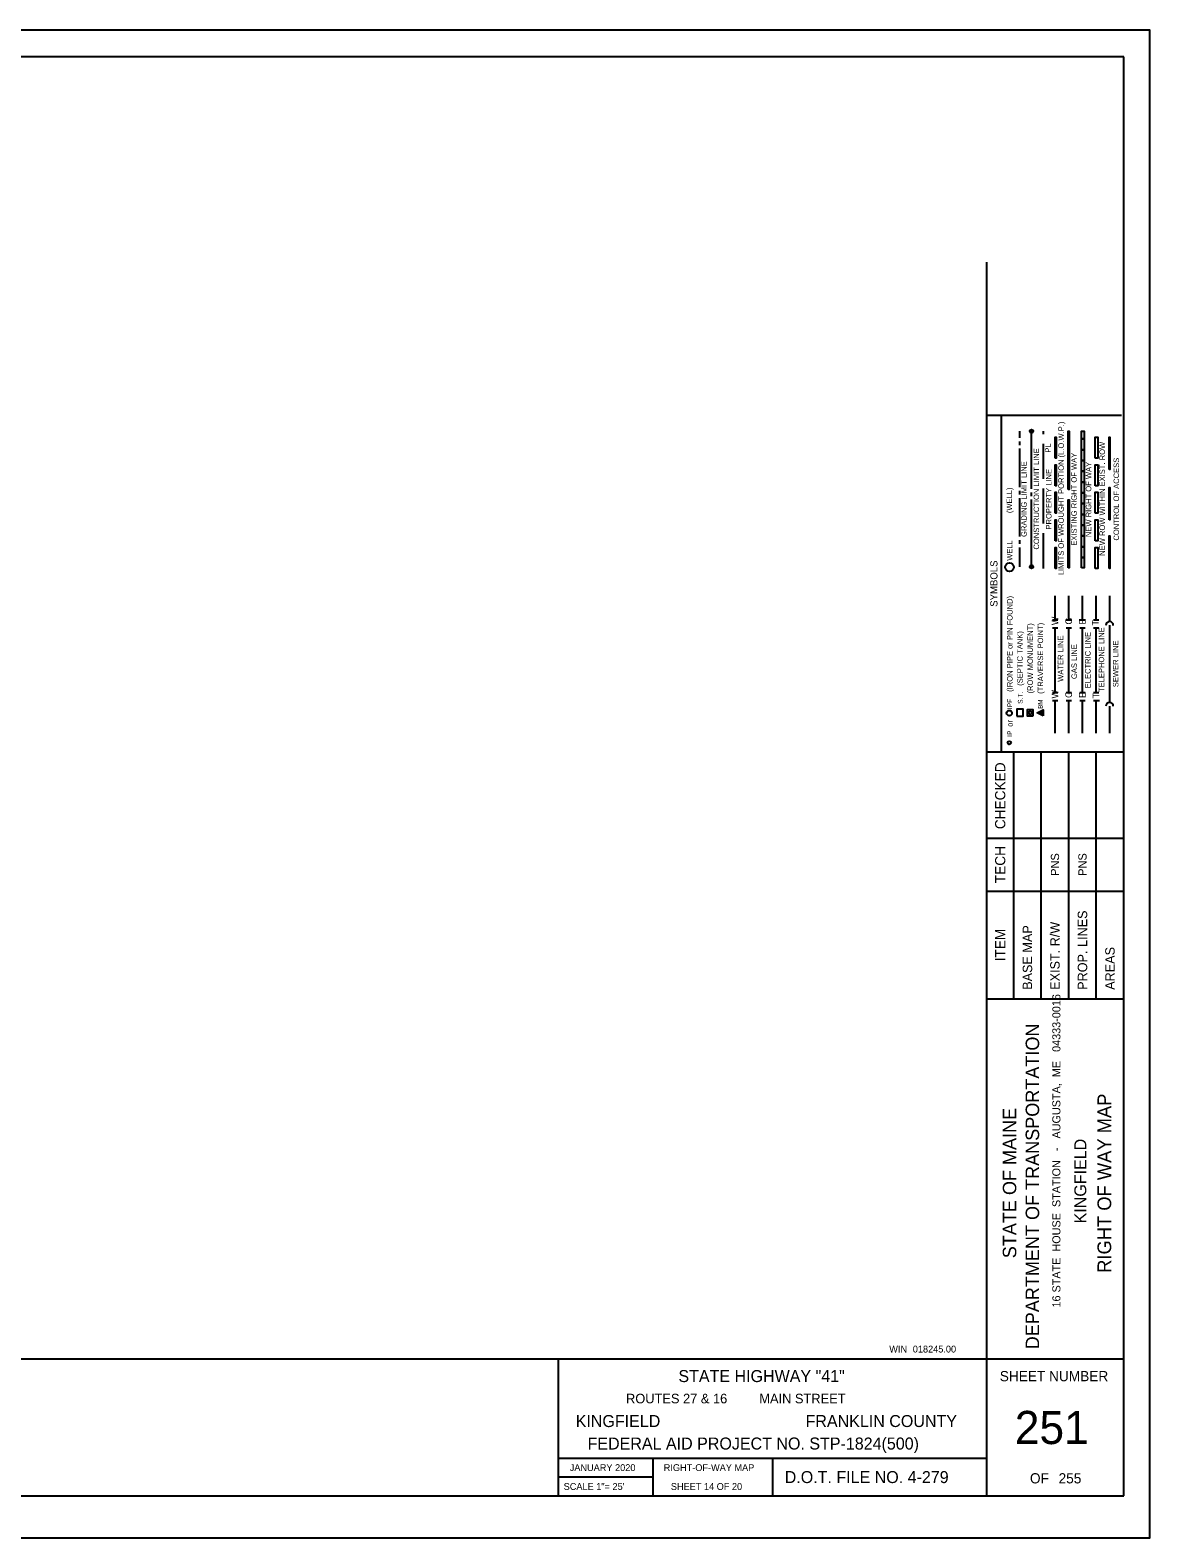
# Model space of a CAD drawing. Extents: x -40 to 810, y -90 to 460.
# Drawn here: x 401 to 810, y -90 to 460 of the extents above; entities that cross this region are included whole.
import ezdxf

# ---------------------------------------------------------------- set-up
doc = ezdxf.new("R2010")
doc.units = 0
for name, color, linetype in [('Border', 7, 'Continuous'), ('HIGHWAY_TITLE', 7, 'Continuous'), ('PLOT BOUNDARY', 7, 'Continuous')]:
    doc.layers.add(name, color=color, linetype=linetype)

msp = doc.modelspace()

# ---------------------------------------------------------------- linework, layer by layer
at = {"layer": 'Border'}
for p, q in [((800, 450), (0, 450)), ((800, -74.98), (800, 450)), ((750, -75), (750, 375.03)), ((750, 319.31), (799.21, 319.31)), ((755.25, 319.31), (755.25, 196.41)), ((762.03, 310.99), (762.03, 313.37)), ((762.03, 308.37), (762.03, 309.68)), ((766.35, 292.38), (766.35, 312.74)), ((770.67, 312.38), (770.67, 313.37)), ((770.67, 296.04), (770.67, 308.84)), ((762.03, 300.02), (762.03, 307.05)), ((762.03, 292.98), (762.03, 300.02)), ((762.03, 290.35), (762.03, 291.67)), ((770.67, 279.71), (770.67, 292.5)), ((762.03, 282), (762.03, 289.04)), ((766.35, 289.76), (766.35, 291.07)), ((766.35, 264.62), (766.35, 288.44)), ((762.03, 274.97), (762.03, 282)), ((770.67, 263.37), (770.67, 276.16)), ((762.03, 272.34), (762.03, 273.66)), ((762.03, 263.99), (762.03, 271.03)), ((774.99, 244.64), (774.99, 253.3)), ((779.97, 244.64), (779.97, 253.3)), ((784.94, 244.64), (784.94, 253.3)), ((789.92, 244.64), (789.92, 253.3)), ((794.9, 244.05), (794.9, 253.3)), ((774.01, 244.64), (775.98, 244.64)), ((778.98, 244.64), (780.95, 244.64)), ((783.96, 244.64), (785.93, 244.64)), ((788.94, 244.64), (790.9, 244.64)), ((794.9, 232.83), (794.9, 242.67)), ((774.01, 241.69), (775.98, 241.69)), ((774.99, 218.06), (774.99, 241.69)), ((778.98, 241.69), (780.95, 241.69)), ((779.97, 229.87), (779.97, 241.69)), ((783.96, 241.69), (785.93, 241.69)), ((784.94, 229.87), (784.94, 241.69)), ((788.94, 241.69), (790.9, 241.69)), ((789.92, 229.87), (789.92, 241.69)), ((794.9, 214.52), (794.9, 232.83)), ((779.97, 218.06), (779.97, 229.87)), ((784.94, 218.06), (784.94, 229.87)), ((789.92, 218.06), (789.92, 229.87)), ((774.01, 218.06), (775.98, 218.06)), ((774.01, 215.11), (775.98, 215.11)), ((774.99, 203.3), (774.99, 215.11)), ((778.98, 218.06), (780.95, 218.06)), ((778.98, 215.11), (780.95, 215.11)), ((779.97, 203.3), (779.97, 215.11)), ((783.96, 218.06), (785.93, 218.06)), ((783.96, 215.11), (785.93, 215.11)), ((784.94, 203.3), (784.94, 215.11)), ((788.94, 218.06), (790.9, 218.06)), ((788.94, 215.11), (791.1, 215.11)), ((789.92, 203.3), (789.92, 215.11)), ((794.9, 203.3), (794.9, 213.14)), ((750, 196.41), (800, 196.41)), ((759.84, 106.28), (759.84, 196.41)), ((769.88, 106.28), (769.88, 196.41)), ((779.92, 106.28), (779.92, 196.41)), ((789.96, 106.28), (789.96, 196.41)), ((750, 164.9), (800, 164.9)), ((750, 145.57), (800, 145.57)), ((750, 106.28), (800, 106.28)), ((0, -24.98), (800, -24.98)), ((593.75, -75), (593.75, -24.98)), ((593.75, -61.24), (750, -61.24)), ((628.12, -61.24), (628.12, -75)), ((671.87, -61.24), (671.87, -75)), ((628.12, -68.12), (593.75, -68.12)), ((0, -75), (800, -75))]:
    msp.add_line(p, q, dxfattribs=at)
for points in [[(774.99, 303.53), (774.99, 311.2), (775.39, 311.2), (775.39, 303.53)], [(779.71, 292.11), (779.71, 313.37), (780.1, 313.37), (780.1, 292.11)], [(784.62, 310.61), (784.62, 313.37), (785.6, 313.37), (785.6, 310.61)], [(784.62, 306.67), (784.62, 310.61), (785.6, 310.61), (785.6, 306.67)], [(789.59, 303.53), (789.59, 311.2), (790.58, 311.2), (790.58, 303.53)], [(794.7, 299.39), (794.7, 311.2), (794.9, 311.2), (794.9, 299.39)], [(784.62, 302.74), (784.62, 306.67), (785.6, 306.67), (785.6, 302.74)], [(784.62, 298.8), (784.62, 302.74), (785.6, 302.74), (785.6, 298.8)], [(774.99, 293.49), (774.99, 301.16), (775.39, 301.16), (775.39, 293.49)], [(784.62, 294.86), (784.62, 298.8), (785.6, 298.8), (785.6, 294.86)], [(789.59, 293.49), (789.59, 301.16), (790.58, 301.16), (790.58, 293.49)], [(784.62, 290.93), (784.62, 294.86), (785.6, 294.86), (785.6, 290.93)], [(794.7, 281.08), (794.7, 292.9), (794.9, 292.9), (794.9, 281.08)], [(774.99, 283.45), (774.99, 291.12), (775.39, 291.12), (775.39, 283.45)], [(779.71, 263.56), (779.71, 288.37), (780.1, 288.37), (780.1, 263.56)], [(784.62, 286.99), (784.62, 290.93), (785.6, 290.93), (785.6, 286.99)], [(784.62, 283.05), (784.62, 286.99), (785.6, 286.99), (785.6, 283.05)], [(789.59, 283.45), (789.59, 291.12), (790.58, 291.12), (790.58, 283.45)], [(774.99, 273.41), (774.99, 281.08), (775.39, 281.08), (775.39, 273.41)], [(784.62, 279.12), (784.62, 283.05), (785.6, 283.05), (785.6, 279.12)], [(789.59, 273.41), (789.59, 281.08), (790.58, 281.08), (790.58, 273.41)], [(784.62, 275.18), (784.62, 279.12), (785.6, 279.12), (785.6, 275.18)], [(784.62, 271.24), (784.62, 275.18), (785.6, 275.18), (785.6, 271.24)], [(794.7, 263.37), (794.7, 275.18), (794.9, 275.18), (794.9, 263.37)], [(774.99, 263.37), (774.99, 271.04), (775.39, 271.04), (775.39, 263.37)], [(784.62, 267.3), (784.62, 271.24), (785.6, 271.24), (785.6, 267.3)], [(789.59, 263.37), (789.59, 271.04), (790.58, 271.04), (790.58, 263.37)], [(784.62, 263.56), (784.62, 267.3), (785.6, 267.3), (785.6, 263.56)]]:
    msp.add_lwpolyline(points, close=True, dxfattribs=at)
for points in [[(760.95, 209.4), (763.31, 209.4), (763.31, 211.96), (760.95, 211.96), (760.95, 209.4)], [(766.98, 209.56), (766.98, 211.81), (764.73, 211.81), (764.73, 209.56), (766.98, 209.56)], [(770.54, 209.62), (768.44, 210.67), (770.54, 211.73), (770.54, 209.62)]]:
    msp.add_lwpolyline(points, dxfattribs=at)
for centre, radius in [((766.35, 313.37), 0.625), ((766.35, 313.37), 0.15), ((766.35, 313.37), 0.05), ((758.29, 263.81), 1.57), ((766.35, 263.99), 0.625), ((766.35, 263.99), 0.15), ((766.35, 263.99), 0.05), ((758.24, 210.59), 0.966), ((765.86, 210.68), 0.563), ((769.86, 210.68), 0.281), ((758.24, 199.76), 0.625)]:
    msp.add_circle(centre, radius, dxfattribs=at)
for centre in [(794.84, 242.59), (794.84, 213.06)]:
    msp.add_arc(centre, 1.35, 0, 180, dxfattribs=at)
at = {"layer": 'PLOT BOUNDARY'}
msp.add_lwpolyline([(-40.47, -90.29), (809.53, -90.29), (809.53, 459.71), (-40.47, 459.71)], close=True, dxfattribs=at)

# ---------------------------------------------------------------- texts
at = {"layer": 'Border'}
for s, height, rotation, p in [('LIMITS OF WROUGHT PORTION (L.O.W.P.)', 1.9996, 90, (778.14, 260.91)), ('PL', 2, 90, (773.35, 305.59)), ('NEW ROW WITHIN EXIST. ROW', 1.9996, 90, (793.14, 267.96)), ('CONSTRUCTION LIMIT LINE', 1.9996, 90, (769.11, 270.22)), ('EXISTING RIGHT OF WAY', 1.9996, 90, (782.86, 271.64)), ('CONTROL OF ACCESS', 1.9996, 90, (798.29, 273.5)), ('GRADING LIMIT LINE', 1.9996, 90, (764.59, 274.83)), ('PROPERTY LINE', 1.9996, 90, (773.63, 277.54)), ('NEW RIGHT OF WAY', 1.9996, 90, (788.16, 274.78)), ('(WELL)', 2, 90, (759.23, 283.52)), ('WELL', 1.969, 90, (759.36, 266.17)), ('SYMBOLS', 2.614, 90, (753.93, 249.35)), ('(IRON PIPE or PIN FOUND)', 1.9996, 90, (759.41, 218.34)), ('(ROW MONUMENT)', 1.9996, 90, (766.85, 217.74)), ('(TRAVERSE POINT)', 1.9996, 90, (770.58, 217.59)), ('W', 2.46, 90, (776.17, 242.67)), ('G', 2.46, 90, (781.15, 242.87)), ('E', 2.46, 90, (786.13, 242.87)), ('T', 2.46, 90, (790.9, 242.47)), ('(SEPTIC TANK)', 1.9996, 90, (763.13, 220.53)), ('WATER LINE', 2, 90, (777.95, 222)), ('ELECTRIC LINE', 1.9996, 90, (787.9, 219.64)), ('TELEPHONE LINE', 1.9996, 90, (792.87, 218.26)), ('GAS LINE', 2, 90, (782.92, 222.98)), ('SEWER LINE', 2, 90, (798.05, 220.03)), ('IPF', 1.749, 90, (759.28, 212.02)), ('S.T.', 1.749, 90, (763.12, 213.93)), ('BM', 1.641, 90, (770.4, 212.13)), ('W', 2.46, 90, (776.17, 215.9)), ('G', 2.46, 90, (781.15, 216.09)), ('E', 2.46, 90, (786.13, 216.09)), ('T', 2.46, 90, (791.1, 215.9)), ('IP', 1.749, 90, (759.28, 201.92)), ('or', 2, 90, (759.47, 205.59)), ('CHECKED', 3.726, 90, (756.78, 168.23)), ('TECH', 3.726, 90, (756.78, 148.51)), ('PROP. LINES', 3.4449, 90, (786.66, 109.63)), ('BASE MAP', 3.445, 90, (766.58, 109.63)), ('EXIST. R/W', 3.445, 90, (776.62, 109.63)), ('ITEM', 3.726, 90, (756.78, 120.01)), ('AREAS', 3.445, 90, (796.7, 109.63)), ('16 STATE  HOUSE  STATION   -   AUGUSTA,  ME   04333-0016', 2.9528, 90, (776.89, -6.27)), ('DEPARTMENT OF TRANSPORTATION', 4.9217, 90, (769.13, -21.51)), ('STATE OF MAINE', 4.9217, 90, (760.79, 11.72)), ('RIGHT OF WAY MAP', 4.9996, 90, (795.42, 6.39)), ('D.O.T. FILE NO. 4-279', 4.375, 360, (676.28, -70.31))]:
    msp.add_text(s, height=height, rotation=rotation, dxfattribs=at).set_placement(p)
for s, height, p in [('SHEET NUMBER', 3.7264, (754.76, -33.16)), ('251', 12.097, (760.24, -56.08)), ('OF', 3.726, (765.77, -70.43)), ('255', 3.726, (776.22, -70.43))]:
    msp.add_text(s, height=height, dxfattribs=at).set_placement(p)
at = {"layer": 'HIGHWAY_TITLE'}
for s, height, rotation, p in [('PNS', 3, 90, (776.4, 151.21)), ('PNS', 3, 90, (786.44, 151.21)), ('KINGFIELD', 4.375, 90, (786.35, 24.41)), ('SCALE 1"= 25\'', 2.5, 360, (595.61, -72.81))]:
    msp.add_text(s, height=height, rotation=rotation, dxfattribs=at).set_placement(p)
for s, height, p in [('WIN', 2.5, (714.44, -22.68)), ('018245.00', 2.5, (723.02, -22.68)), ('STATE HIGHWAY "41"', 4.375, (637.49, -33.46)), ('ROUTES 27 & 16         MAIN STREET', 3.5, (618.37, -41.23)), ('KINGFIELD', 4.375, (600, -49.87)), ('FRANKLIN COUNTY', 4.375, (683.88, -49.87)), ('FEDERAL AID PROJECT NO. STP-1824(500)', 4.375, (604.33, -58.07)), ('JANUARY 2020', 2.5, (597.83, -65.93)), ('RIGHT-OF-WAY MAP', 2.5, (632.13, -65.93)), ('SHEET 14 OF 20', 2.5, (634.73, -72.81))]:
    msp.add_text(s, height=height, dxfattribs=at).set_placement(p)

doc.saveas('drawing.dxf')
